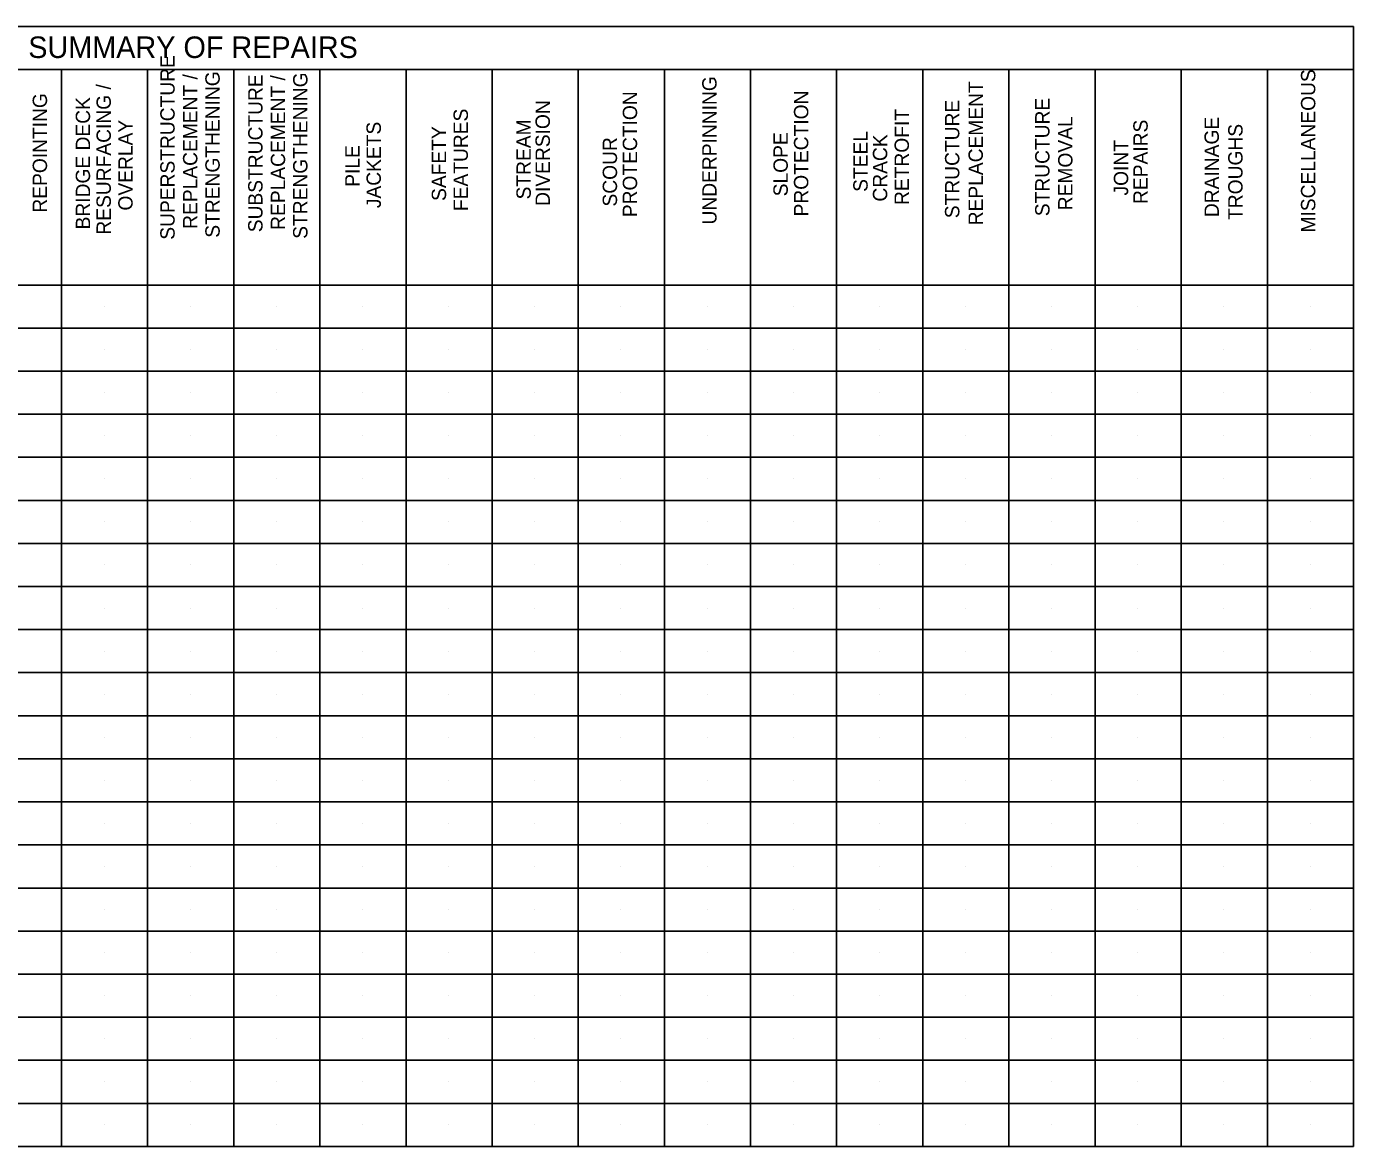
# Model space of a CAD drawing. Extents: x 3.4 to 29.9, y 7.8 to 20.1.
# Drawn here: x 15.32 to 29.88, y 7.79 to 20.08 of the extents above; entities that cross this region are included whole.
import ezdxf

# ---------------------------------------------------------------- set-up
doc = ezdxf.new("R2010")
doc.units = 0
doc.layers.add('G-ANNO-NOTE', color=7, linetype='Continuous')

msp = doc.modelspace()

# ---------------------------------------------------------------- linework, layer by layer
at = {"layer": 'G-ANNO-NOTE'}
for p, q in [((3.421, 20.077), (29.877, 20.077)), ((29.877, 20.077), (29.877, 7.794)), ((3.421, 19.605), (29.877, 19.605)), ((15.704, 17.242), (15.704, 19.605)), ((16.649, 17.242), (16.649, 19.605)), ((17.594, 17.242), (17.594, 19.605)), ((18.539, 17.242), (18.539, 19.605)), ((19.484, 17.242), (19.484, 19.605)), ((20.429, 17.242), (20.429, 19.605)), ((21.373, 17.242), (21.373, 19.605)), ((22.318, 17.242), (22.318, 19.605)), ((23.263, 17.242), (23.263, 19.605)), ((24.208, 17.242), (24.208, 19.605)), ((25.153, 17.242), (25.153, 19.605)), ((26.098, 17.242), (26.098, 19.605)), ((27.043, 17.242), (27.043, 19.605)), ((27.988, 17.242), (27.988, 19.605)), ((28.933, 17.242), (28.933, 19.605)), ((3.421, 17.242), (29.877, 17.242)), ((15.704, 17.242), (15.704, 7.794)), ((16.649, 17.242), (16.649, 7.794)), ((17.594, 17.242), (17.594, 7.794)), ((18.539, 17.242), (18.539, 7.794)), ((19.484, 17.242), (19.484, 7.794)), ((20.429, 17.242), (20.429, 7.794)), ((21.373, 17.242), (21.373, 7.794)), ((22.318, 17.242), (22.318, 7.794)), ((23.263, 17.242), (23.263, 7.794)), ((24.208, 17.242), (24.208, 7.794)), ((25.153, 17.242), (25.153, 7.794)), ((26.098, 17.242), (26.098, 7.794)), ((27.043, 17.242), (27.043, 7.794)), ((27.988, 17.242), (27.988, 7.794)), ((28.933, 17.242), (28.933, 7.794)), ((16.173, 17.006), (16.173, 17.006)), ((16.173, 17.006), (16.173, 17.006)), ((17.118, 17.006), (17.118, 17.006)), ((17.118, 17.006), (17.118, 17.006)), ((18.063, 17.006), (18.063, 17.006)), ((18.063, 17.006), (18.063, 17.006)), ((19.007, 17.006), (19.007, 17.006)), ((19.007, 17.006), (19.007, 17.006)), ((19.952, 17.006), (19.952, 17.006)), ((19.952, 17.006), (19.952, 17.006)), ((20.897, 17.006), (20.897, 17.006)), ((20.897, 17.006), (20.897, 17.006)), ((21.842, 17.006), (21.842, 17.006)), ((21.842, 17.006), (21.842, 17.006)), ((22.787, 17.006), (22.787, 17.006)), ((22.787, 17.006), (22.787, 17.006)), ((23.732, 17.006), (23.732, 17.006)), ((23.732, 17.006), (23.732, 17.006)), ((24.677, 17.006), (24.677, 17.006)), ((24.677, 17.006), (24.677, 17.006)), ((25.622, 17.006), (25.622, 17.006)), ((25.622, 17.006), (25.622, 17.006)), ((26.567, 17.006), (26.567, 17.006)), ((26.567, 17.006), (26.567, 17.006)), ((27.511, 17.006), (27.511, 17.006)), ((27.511, 17.006), (27.511, 17.006)), ((28.456, 17.006), (28.456, 17.006)), ((28.456, 17.006), (28.456, 17.006)), ((29.401, 17.006), (29.401, 17.006)), ((29.401, 17.006), (29.401, 17.006)), ((3.421, 16.77), (29.877, 16.77)), ((16.173, 16.534), (16.173, 16.534)), ((16.173, 16.534), (16.173, 16.534)), ((16.173, 16.534), (16.173, 16.534)), ((17.118, 16.534), (17.118, 16.534)), ((17.118, 16.534), (17.118, 16.534)), ((17.118, 16.534), (17.118, 16.534)), ((18.063, 16.534), (18.063, 16.534)), ((18.063, 16.534), (18.063, 16.534)), ((18.063, 16.534), (18.063, 16.534)), ((19.007, 16.534), (19.007, 16.534)), ((19.007, 16.534), (19.007, 16.534)), ((19.007, 16.534), (19.007, 16.534)), ((19.952, 16.534), (19.952, 16.534)), ((19.952, 16.534), (19.952, 16.534)), ((19.952, 16.534), (19.952, 16.534)), ((20.897, 16.534), (20.897, 16.534)), ((20.897, 16.534), (20.897, 16.534)), ((20.897, 16.534), (20.897, 16.534)), ((21.842, 16.534), (21.842, 16.534)), ((21.842, 16.534), (21.842, 16.534)), ((21.842, 16.534), (21.842, 16.534)), ((22.787, 16.534), (22.787, 16.534)), ((22.787, 16.534), (22.787, 16.534)), ((22.787, 16.534), (22.787, 16.534)), ((23.732, 16.534), (23.732, 16.534)), ((23.732, 16.534), (23.732, 16.534)), ((23.732, 16.534), (23.732, 16.534)), ((24.677, 16.534), (24.677, 16.534)), ((24.677, 16.534), (24.677, 16.534)), ((24.677, 16.534), (24.677, 16.534)), ((25.622, 16.534), (25.622, 16.534)), ((25.622, 16.534), (25.622, 16.534)), ((25.622, 16.534), (25.622, 16.534)), ((26.567, 16.534), (26.567, 16.534)), ((26.567, 16.534), (26.567, 16.534)), ((26.567, 16.534), (26.567, 16.534)), ((27.511, 16.534), (27.511, 16.534)), ((27.511, 16.534), (27.511, 16.534)), ((27.511, 16.534), (27.511, 16.534)), ((28.456, 16.534), (28.456, 16.534)), ((28.456, 16.534), (28.456, 16.534)), ((28.456, 16.534), (28.456, 16.534)), ((29.401, 16.534), (29.401, 16.534)), ((29.401, 16.534), (29.401, 16.534)), ((29.401, 16.534), (29.401, 16.534)), ((3.421, 16.298), (29.877, 16.298)), ((16.173, 16.061), (16.173, 16.061)), ((17.118, 16.061), (17.118, 16.061)), ((18.063, 16.061), (18.063, 16.061)), ((19.007, 16.061), (19.007, 16.061)), ((19.952, 16.061), (19.952, 16.061)), ((20.897, 16.061), (20.897, 16.061)), ((21.842, 16.061), (21.842, 16.061)), ((22.787, 16.061), (22.787, 16.061)), ((23.732, 16.061), (23.732, 16.061)), ((24.677, 16.061), (24.677, 16.061)), ((25.622, 16.061), (25.622, 16.061)), ((26.567, 16.061), (26.567, 16.061)), ((27.511, 16.061), (27.511, 16.061)), ((28.456, 16.061), (28.456, 16.061)), ((29.401, 16.061), (29.401, 16.061)), ((3.421, 15.825), (29.877, 15.825)), ((16.173, 15.589), (16.173, 15.589)), ((17.118, 15.589), (17.118, 15.589)), ((18.063, 15.589), (18.063, 15.589)), ((19.007, 15.589), (19.007, 15.589)), ((19.952, 15.589), (19.952, 15.589)), ((20.897, 15.589), (20.897, 15.589)), ((21.842, 15.589), (21.842, 15.589)), ((22.787, 15.589), (22.787, 15.589)), ((23.732, 15.589), (23.732, 15.589)), ((24.677, 15.589), (24.677, 15.589)), ((25.622, 15.589), (25.622, 15.589)), ((26.567, 15.589), (26.567, 15.589)), ((27.511, 15.589), (27.511, 15.589)), ((28.456, 15.589), (28.456, 15.589)), ((29.401, 15.589), (29.401, 15.589)), ((3.421, 15.353), (29.877, 15.353)), ((16.173, 15.116), (16.173, 15.116)), ((17.118, 15.116), (17.118, 15.116)), ((18.063, 15.116), (18.063, 15.116)), ((19.007, 15.116), (19.007, 15.116)), ((19.952, 15.116), (19.952, 15.116)), ((20.897, 15.116), (20.897, 15.116)), ((21.842, 15.116), (21.842, 15.116)), ((22.787, 15.116), (22.787, 15.116)), ((23.732, 15.116), (23.732, 15.116)), ((24.677, 15.116), (24.677, 15.116)), ((25.622, 15.116), (25.622, 15.116)), ((26.567, 15.116), (26.567, 15.116)), ((27.511, 15.116), (27.511, 15.116)), ((28.456, 15.116), (28.456, 15.116)), ((29.401, 15.116), (29.401, 15.116)), ((3.421, 14.88), (29.877, 14.88)), ((16.173, 14.644), (16.173, 14.644)), ((17.118, 14.644), (17.118, 14.644)), ((18.063, 14.644), (18.063, 14.644)), ((19.007, 14.644), (19.007, 14.644)), ((19.952, 14.644), (19.952, 14.644)), ((20.897, 14.644), (20.897, 14.644)), ((21.842, 14.644), (21.842, 14.644)), ((22.787, 14.644), (22.787, 14.644)), ((23.732, 14.644), (23.732, 14.644)), ((24.677, 14.644), (24.677, 14.644)), ((25.622, 14.644), (25.622, 14.644)), ((26.567, 14.644), (26.567, 14.644)), ((27.511, 14.644), (27.511, 14.644)), ((28.456, 14.644), (28.456, 14.644)), ((29.401, 14.644), (29.401, 14.644)), ((3.421, 14.408), (29.877, 14.408)), ((16.173, 14.172), (16.173, 14.172)), ((17.118, 14.172), (17.118, 14.172)), ((18.063, 14.172), (18.063, 14.172)), ((19.007, 14.172), (19.007, 14.172)), ((19.952, 14.172), (19.952, 14.172)), ((20.897, 14.172), (20.897, 14.172)), ((21.842, 14.172), (21.842, 14.172)), ((22.787, 14.172), (22.787, 14.172)), ((23.732, 14.172), (23.732, 14.172)), ((24.677, 14.172), (24.677, 14.172)), ((25.622, 14.172), (25.622, 14.172)), ((26.567, 14.172), (26.567, 14.172)), ((27.511, 14.172), (27.511, 14.172)), ((28.456, 14.172), (28.456, 14.172)), ((29.401, 14.172), (29.401, 14.172)), ((3.421, 13.935), (29.877, 13.935)), ((16.173, 13.699), (16.173, 13.699)), ((17.118, 13.699), (17.118, 13.699)), ((18.063, 13.699), (18.063, 13.699)), ((19.007, 13.699), (19.007, 13.699)), ((19.952, 13.699), (19.952, 13.699)), ((20.897, 13.699), (20.897, 13.699)), ((21.842, 13.699), (21.842, 13.699)), ((22.787, 13.699), (22.787, 13.699)), ((23.732, 13.699), (23.732, 13.699)), ((24.677, 13.699), (24.677, 13.699)), ((25.622, 13.699), (25.622, 13.699)), ((26.567, 13.699), (26.567, 13.699)), ((27.511, 13.699), (27.511, 13.699)), ((28.456, 13.699), (28.456, 13.699)), ((29.401, 13.699), (29.401, 13.699)), ((3.421, 13.463), (29.877, 13.463)), ((16.173, 13.227), (16.173, 13.227)), ((17.118, 13.227), (17.118, 13.227)), ((18.063, 13.227), (18.063, 13.227)), ((19.007, 13.227), (19.007, 13.227)), ((19.952, 13.227), (19.952, 13.227)), ((20.897, 13.227), (20.897, 13.227)), ((21.842, 13.227), (21.842, 13.227)), ((22.787, 13.227), (22.787, 13.227)), ((23.732, 13.227), (23.732, 13.227)), ((24.677, 13.227), (24.677, 13.227)), ((25.622, 13.227), (25.622, 13.227)), ((26.567, 13.227), (26.567, 13.227)), ((27.511, 13.227), (27.511, 13.227)), ((28.456, 13.227), (28.456, 13.227)), ((29.401, 13.227), (29.401, 13.227)), ((3.421, 12.991), (29.877, 12.991)), ((16.173, 12.754), (16.173, 12.754)), ((17.118, 12.754), (17.118, 12.754)), ((18.063, 12.754), (18.063, 12.754)), ((19.007, 12.754), (19.007, 12.754)), ((19.952, 12.754), (19.952, 12.754)), ((20.897, 12.754), (20.897, 12.754)), ((21.842, 12.754), (21.842, 12.754)), ((22.787, 12.754), (22.787, 12.754)), ((23.732, 12.754), (23.732, 12.754)), ((24.677, 12.754), (24.677, 12.754)), ((25.622, 12.754), (25.622, 12.754)), ((26.567, 12.754), (26.567, 12.754)), ((27.511, 12.754), (27.511, 12.754)), ((28.456, 12.754), (28.456, 12.754)), ((29.401, 12.754), (29.401, 12.754)), ((3.421, 12.518), (29.877, 12.518)), ((16.173, 12.282), (16.173, 12.282)), ((17.118, 12.282), (17.118, 12.282)), ((18.063, 12.282), (18.063, 12.282)), ((19.007, 12.282), (19.007, 12.282)), ((19.952, 12.282), (19.952, 12.282)), ((20.897, 12.282), (20.897, 12.282)), ((21.842, 12.282), (21.842, 12.282)), ((22.787, 12.282), (22.787, 12.282)), ((23.732, 12.282), (23.732, 12.282)), ((24.677, 12.282), (24.677, 12.282)), ((25.622, 12.282), (25.622, 12.282)), ((26.567, 12.282), (26.567, 12.282)), ((27.511, 12.282), (27.511, 12.282)), ((28.456, 12.282), (28.456, 12.282)), ((29.401, 12.282), (29.401, 12.282)), ((3.421, 12.046), (29.877, 12.046)), ((16.173, 11.809), (16.173, 11.809)), ((17.118, 11.809), (17.118, 11.809)), ((18.063, 11.809), (18.063, 11.809)), ((19.007, 11.809), (19.007, 11.809)), ((19.952, 11.809), (19.952, 11.809)), ((20.897, 11.809), (20.897, 11.809)), ((21.842, 11.809), (21.842, 11.809)), ((22.787, 11.809), (22.787, 11.809)), ((23.732, 11.809), (23.732, 11.809)), ((24.677, 11.809), (24.677, 11.809)), ((25.622, 11.809), (25.622, 11.809)), ((26.567, 11.809), (26.567, 11.809)), ((27.511, 11.809), (27.511, 11.809)), ((28.456, 11.809), (28.456, 11.809)), ((29.401, 11.809), (29.401, 11.809)), ((3.421, 11.573), (29.877, 11.573)), ((16.173, 11.337), (16.173, 11.337)), ((17.118, 11.337), (17.118, 11.337)), ((18.063, 11.337), (18.063, 11.337)), ((19.007, 11.337), (19.007, 11.337)), ((19.952, 11.337), (19.952, 11.337)), ((20.897, 11.337), (20.897, 11.337)), ((21.842, 11.337), (21.842, 11.337)), ((22.787, 11.337), (22.787, 11.337)), ((23.732, 11.337), (23.732, 11.337)), ((24.677, 11.337), (24.677, 11.337)), ((25.622, 11.337), (25.622, 11.337)), ((26.567, 11.337), (26.567, 11.337)), ((27.511, 11.337), (27.511, 11.337)), ((28.456, 11.337), (28.456, 11.337)), ((29.401, 11.337), (29.401, 11.337)), ((3.421, 11.101), (29.877, 11.101)), ((16.173, 10.864), (16.173, 10.864)), ((16.173, 10.864), (16.173, 10.864)), ((17.118, 10.864), (17.118, 10.864)), ((17.118, 10.864), (17.118, 10.864)), ((18.063, 10.864), (18.063, 10.864)), ((18.063, 10.864), (18.063, 10.864)), ((19.007, 10.864), (19.007, 10.864)), ((19.007, 10.864), (19.007, 10.864)), ((19.952, 10.864), (19.952, 10.864)), ((19.952, 10.864), (19.952, 10.864)), ((20.897, 10.864), (20.897, 10.864)), ((20.897, 10.864), (20.897, 10.864)), ((21.842, 10.864), (21.842, 10.864)), ((21.842, 10.864), (21.842, 10.864)), ((22.787, 10.864), (22.787, 10.864)), ((22.787, 10.864), (22.787, 10.864)), ((23.732, 10.864), (23.732, 10.864)), ((23.732, 10.864), (23.732, 10.864)), ((24.677, 10.864), (24.677, 10.864)), ((24.677, 10.864), (24.677, 10.864)), ((25.622, 10.864), (25.622, 10.864)), ((25.622, 10.864), (25.622, 10.864)), ((26.567, 10.864), (26.567, 10.864)), ((26.567, 10.864), (26.567, 10.864)), ((27.511, 10.864), (27.511, 10.864)), ((27.511, 10.864), (27.511, 10.864)), ((28.456, 10.864), (28.456, 10.864)), ((28.456, 10.864), (28.456, 10.864)), ((29.401, 10.864), (29.401, 10.864)), ((29.401, 10.864), (29.401, 10.864)), ((3.421, 10.628), (29.877, 10.628)), ((16.173, 10.392), (16.173, 10.392)), ((17.118, 10.392), (17.118, 10.392)), ((18.063, 10.392), (18.063, 10.392)), ((19.007, 10.392), (19.007, 10.392)), ((19.952, 10.392), (19.952, 10.392)), ((20.897, 10.392), (20.897, 10.392)), ((21.842, 10.392), (21.842, 10.392)), ((22.787, 10.392), (22.787, 10.392)), ((23.732, 10.392), (23.732, 10.392)), ((24.677, 10.392), (24.677, 10.392)), ((25.622, 10.392), (25.622, 10.392)), ((26.567, 10.392), (26.567, 10.392)), ((27.511, 10.392), (27.511, 10.392)), ((28.456, 10.392), (28.456, 10.392)), ((29.401, 10.392), (29.401, 10.392)), ((3.421, 10.156), (29.877, 10.156)), ((16.173, 9.92), (16.173, 9.92)), ((17.118, 9.92), (17.118, 9.92)), ((18.063, 9.92), (18.063, 9.92)), ((19.007, 9.92), (19.007, 9.92)), ((19.952, 9.92), (19.952, 9.92)), ((20.897, 9.92), (20.897, 9.92)), ((21.842, 9.92), (21.842, 9.92)), ((22.787, 9.92), (22.787, 9.92)), ((23.732, 9.92), (23.732, 9.92)), ((24.677, 9.92), (24.677, 9.92)), ((25.622, 9.92), (25.622, 9.92)), ((26.567, 9.92), (26.567, 9.92)), ((27.511, 9.92), (27.511, 9.92)), ((28.456, 9.92), (28.456, 9.92)), ((29.401, 9.92), (29.401, 9.92)), ((3.421, 9.683), (29.877, 9.683)), ((16.173, 9.447), (16.173, 9.447)), ((17.118, 9.447), (17.118, 9.447)), ((18.063, 9.447), (18.063, 9.447)), ((19.007, 9.447), (19.007, 9.447)), ((19.952, 9.447), (19.952, 9.447)), ((20.897, 9.447), (20.897, 9.447)), ((21.842, 9.447), (21.842, 9.447)), ((22.787, 9.447), (22.787, 9.447)), ((23.732, 9.447), (23.732, 9.447)), ((24.677, 9.447), (24.677, 9.447)), ((25.622, 9.447), (25.622, 9.447)), ((26.567, 9.447), (26.567, 9.447)), ((27.511, 9.447), (27.511, 9.447)), ((28.456, 9.447), (28.456, 9.447)), ((29.401, 9.447), (29.401, 9.447)), ((3.421, 9.211), (29.877, 9.211)), ((16.173, 8.975), (16.173, 8.975)), ((17.118, 8.975), (17.118, 8.975)), ((18.063, 8.975), (18.063, 8.975)), ((19.007, 8.975), (19.007, 8.975)), ((19.952, 8.975), (19.952, 8.975)), ((20.897, 8.975), (20.897, 8.975)), ((21.842, 8.975), (21.842, 8.975)), ((22.787, 8.975), (22.787, 8.975)), ((23.732, 8.975), (23.732, 8.975)), ((24.677, 8.975), (24.677, 8.975)), ((25.622, 8.975), (25.622, 8.975)), ((26.567, 8.975), (26.567, 8.975)), ((27.511, 8.975), (27.511, 8.975)), ((28.456, 8.975), (28.456, 8.975)), ((29.401, 8.975), (29.401, 8.975)), ((3.421, 8.739), (29.877, 8.739)), ((16.173, 8.502), (16.173, 8.502)), ((17.118, 8.502), (17.118, 8.502)), ((18.063, 8.502), (18.063, 8.502)), ((19.007, 8.502), (19.007, 8.502)), ((19.952, 8.502), (19.952, 8.502)), ((20.897, 8.502), (20.897, 8.502)), ((21.842, 8.502), (21.842, 8.502)), ((22.787, 8.502), (22.787, 8.502)), ((23.732, 8.502), (23.732, 8.502)), ((24.677, 8.502), (24.677, 8.502)), ((25.622, 8.502), (25.622, 8.502)), ((26.567, 8.502), (26.567, 8.502)), ((27.511, 8.502), (27.511, 8.502)), ((28.456, 8.502), (28.456, 8.502)), ((29.401, 8.502), (29.401, 8.502)), ((3.421, 8.266), (29.877, 8.266)), ((16.173, 8.03), (16.173, 8.03)), ((17.118, 8.03), (17.118, 8.03)), ((18.063, 8.03), (18.063, 8.03)), ((19.007, 8.03), (19.007, 8.03)), ((19.952, 8.03), (19.952, 8.03)), ((20.897, 8.03), (20.897, 8.03)), ((21.842, 8.03), (21.842, 8.03)), ((22.787, 8.03), (22.787, 8.03)), ((23.732, 8.03), (23.732, 8.03)), ((24.677, 8.03), (24.677, 8.03)), ((25.622, 8.03), (25.622, 8.03)), ((26.567, 8.03), (26.567, 8.03)), ((27.511, 8.03), (27.511, 8.03)), ((28.456, 8.03), (28.456, 8.03)), ((29.401, 8.03), (29.401, 8.03)), ((3.421, 7.794), (29.877, 7.794))]:
    msp.add_line(p, q, dxfattribs=at)

# ---------------------------------------------------------------- texts
msp.add_text('SUMMARY OF REPAIRS', height=0.23622, dxfattribs=at).set_placement((15.34, 19.732))
for s, height, p in [('SUPERSTRUCTURE', 0.15748, (16.946, 17.739)), ('REPLACEMENT /', 0.15748, (17.195, 17.858)), ('STRENGTHENING ', 0.15748, (17.44, 17.761)), ('SUBSTRUCTURE', 0.15748, (17.91, 17.821)), ('REPLACEMENT /', 0.15748, (18.158, 17.847)), ('STRENGTHENING ', 0.15748, (18.403, 17.749)), ('UNDERPINNING', 0.15748, (22.891, 17.906)), ('MISCELLANEOUS', 0.15748, (29.459, 17.818)), ('RESURFACING /', 0.15748, (16.246, 17.795)), ('REPLACEMENT', 0.15748, (25.812, 17.897)), ('REPOINTING', 0.1575, (15.546, 18.036)), ('BRIDGE DECK', 0.15748, (16.018, 17.852)), ('DIVERSION', 0.1575, (21.062, 18.11)), ('PROTECTION', 0.1575, (22.019, 17.986)), ('PROTECTION', 0.1575, (23.897, 17.994)), ('STRUCTURE', 0.1575, (25.554, 17.975)), ('STRUCTURE', 0.1575, (26.543, 17.997)), ('FEATURES', 0.1575, (20.163, 18.053)), ('RETROFIT', 0.1575, (25.001, 18.12)), ('REMOVAL', 0.1575, (26.795, 18.062)), ('DRAINAGE', 0.1575, (28.401, 17.987)), ('OVERLAY', 0.1575, (16.485, 18.059)), ('JACKETS', 0.1575, (19.208, 18.085)), ('SAFETY', 0.1575, (19.924, 18.164)), ('STREAM', 0.1575, (20.853, 18.181)), ('STEEL ', 0.1575, (24.548, 18.264)), ('REPAIRS', 0.1575, (27.62, 18.131)), ('TROUGHS ', 0.1575, (28.661, 17.956)), ('SCOUR', 0.1575, (21.799, 18.103)), ('SLOPE', 0.1575, (23.672, 18.215)), ('CRACK', 0.1575, (24.763, 18.157)), ('JOINT', 0.1575, (27.406, 18.224)), ('PILE', 0.1575, (18.974, 18.319))]:
    msp.add_text(s, height=height, rotation=90, dxfattribs=at).set_placement(p)

doc.saveas('drawing.dxf')
